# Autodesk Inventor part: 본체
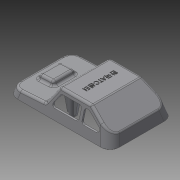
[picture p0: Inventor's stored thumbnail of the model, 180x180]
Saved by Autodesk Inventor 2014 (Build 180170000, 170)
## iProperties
Created: 2015-05
Part Number: 본체
Material: Generic
Document SubType Name: Modeling
Designer: Administrator
Density: 1 g/cm^3
Appearance: Default
Mass: 30.9016 g
Surface Area: 310.511 cm^2
Volume: 30.9016 cm^3
Author: Administrator
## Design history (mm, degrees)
sketch "스케치1"
  geometry: L1 (-61, -38)-(61, -38); L2 (61, -38)-(61, 38); L3 (61, 38)-(-61, 38); L4 (-61, 38)-(-61, -38); L5 (-61, -38)-(61, 38); L6 (61, -38)-(-61, 38); 1 further point
  constraints: 12 end point, 2 midpoint, 2 parallel, 1 horizontal, 1 perpendicular
  dimensions: "d0" = 122 distance of L3.end L2.end; "d1" = 76 distance of L2.end L1.end
extrude "돌출1" new body sketch "스케치1" distance "d2" = 30; taper "d3" = -15 deg
sketch "스케치3"
  geometry: L1 (-31, 30)-(-61, 30); L2 (-61, 30)-(-61, 10); L3 (-61, 10)-(-31, 30); L4 (52.962, 30)-(-52.962, 30) reference; L5 (-61, 0)-(61, 0) reference; 1 further point
  constraints: 6 end point, 1 collinear, 1 horizontal, 1 perpendicular, 1 point on line
  dimensions: "d4" = 30 distance from line of L2 L1.start; "d5" = 20 distance from line of L2.end L1
extrude "돌출2" cut sketch "스케치3" stored distance "d6" = 30; taper "d7" = 0 deg
sketch "스케치4"
  geometry: L1 (61, 8)-(19, 10.201); L2 (19, 10.201)-(6.628, 30); L3 (52.962, 30)-(-31, 30) reference; L4 (61, 8)-(61, 0); L5 (61, 0)-(52.962, 30) reference; L6 (-61, 0)-(61, 0) reference; L7 (6.628, 30)-(61, 30); L8 (61, 30)-(61, 8); 1 further point
  constraints: 10 end point, 2 perpendicular, 1 parallel, 1 point on line
  dimensions: "d8" = 8 distance of L4.end L1.start; "d9" = 3 deg angle of L6 L1; "d10" = 42 horizontal distance of L1.end L1.start; "d11" = 125 deg angle of L1 L2
extrude "돌출3" cut sketch "스케치4" stored distance "d12" = 30; taper "d13" = 0 deg
fillet "모깎기1" dims "d14" = 12
fillet "모깎기2" dims "d15" = 3
sketch "스케치5"
  geometry: L1 (-29.915, 45.985)-(-9.915, 45.985); L2 (-9.915, 45.985)-(-9.915, 19.985); L3 (-9.915, 19.985)-(-29.915, 19.985); L4 (-29.915, 19.985)-(-29.915, 45.985); L5 (-40.915, 59.394)-(-40.915, 6.577) reference; 2 further points
  constraints: 8 end point, 2 parallel, 1 horizontal, 1 horizontal alignment, 1 midpoint, 1 perpendicular
  dimensions: "d16" = 11 distance between parallel lines of L4 L5; "d17" = 20 distance between parallel lines of L2 L4; "d18" = 26 distance between parallel lines of L3 L1
extrude "돌출4" join sketch "스케치5" distance "d19" = 5; taper "d20" = 0 deg
node "작업 평면1"
sketch "스케치6"
  geometry: L1 (-26.409, 0)-(-38, 0) reference; L2 (38, 0)-(26.409, 0) reference; L3 (-25, 0)-(-17, 0); L4 (-14, 0)-(-6, 0); L5 (6, 0)-(14, 0); L6 (17, 0)-(25, 0); A1 r 4 centre (-10, 0) between (-6, 0) and (-14, 0); A2 r 4 centre (-21, 0) between (-17, 0) and (-25, 0); A3 r 4 centre (10, 0) between (14, 0) and (6, 0); A4 r 4 centre (21, 0) between (25, 0) and (17, 0); 1 further point
  constraints: 8 end point, 8 point on circle, 4 centre point, 4 horizontal alignment, 9 other
  dimensions: "d24" = 8 diameter of A1; "d25" = 8 diameter of A2; "d26" = 8 diameter of A3; "d27" = 8 diameter of A4; "d28" = 10 distance of point (0, 0) A1.centre; "d29" = 20 distance of A3.centre A1.centre; "d30" = 11 distance of A1.centre A2.centre; "d31" = 11 distance of A3.centre A4.centre
feature "쉘1" dims "d32" = 2
extrude "돌출5" join sketch "스케치6" stored distance "d33" = 5; taper "d34" = 0 deg
sketch "스케치7"
  geometry: L1 (-58.929, -26.27)-(-58.929, 26.27) reference; L2 (-49.27, 35.929)-(49.27, 35.929) reference; L3 (58.929, 26.27)-(58.929, -26.27) reference; L4 (49.27, -35.929)-(-49.27, -35.929) reference; L5 (49.27, 36.929)-(-49.27, 36.929); L6 (-59.929, 26.27)-(-59.929, -26.27); L7 (-49.27, -36.929)-(49.27, -36.929); L8 (59.929, -26.27)-(59.929, 26.27); 5 further points; 4 other entities
  constraints: 8 end point, 7 parallel, 16 other
  dimensions: "d35" = 1 distance between parallel lines of L2 L5
extrude "돌출6" join sketch "스케치7" distance "d36" = 1; taper "d37" = 0 deg
sketch "스케치8"
  geometry: L1 (4.965, 30)-(-30.092, 30) reference; L2 (18.172, 11.526)-(7.51, 28.59) reference; L3 (-31.756, 29.496)-(-46.213, 19.858) reference; L4 (13.23, 10)-(3.857, 25); L5 (3.857, 25)-(-20.77, 25); L6 (-20.77, 25)-(-20.77, 10); L7 (13.23, 10)-(-20.77, 10); L8 (-23.986, 25)-(-29.486, 25); L9 (-29.486, 25)-(-51.986, 10); L10 (-51.986, 10)-(-23.986, 10); L11 (-23.986, 10)-(-23.986, 25); 1 further point
  constraints: 16 end point, 5 parallel, 3 perpendicular
  dimensions: "d38" = 5 distance between parallel lines of L4 L2; "d39" = 5 distance between parallel lines of L5 L1; "d40" = 34 distance from line of L6 L4.start; "d41" = 15 distance between parallel lines of L7 L5; "d42" = 5 distance between parallel lines of L8 L1; "d43" = 5 distance between parallel lines of L3 L9; "d44" = 15 distance between parallel lines of L10 L8; "d45" = 28 distance from line of L11 L9.end
extrude "돌출7" cut sketch "스케치8" stored distance "d46" = 1; taper "d47" = 0 deg
fillet "모깎기5" dims "d48" = 3
fillet "모깎기6" dims "d49" = 3
sketch "스케치9"
  geometry: C1 r 3 at (0, -22); C2 r 3 at (0, 22); C3 r 3 at (40, 0); C4 r 3 at (-40, 0); 1 further point
  constraints: 4 centre point, 2 horizontal alignment, 2 vertical alignment
  dimensions: "d50" = 6 diameter of C1; "d51" = 6 diameter of C2; "d52" = 6 diameter of C3; "d53" = 6 diameter of C4; "d54" = 40 distance of point (0, 0) C4.centre; "d55" = 40 distance of point (0, 0) C3.centre; "d56" = 44 distance of C2.centre C1.centre; "d57" = 22 distance of C2.centre point (0, 0)
extrude "돌출8" join sketch "스케치9" stored distance "d58" = 2; taper "d59" = 2 deg
node "작업 평면2"
sketch "스케치10"
  geometry: L1 (5, -21)-(-5, -21); L2 (-5, -21)-(-5, -23); L3 (-5, -23)-(5, -23); L4 (5, -23)-(5, -21); L5 (5, -21)-(-5, -23); L6 (-5, -21)-(5, -23); L7 (-35, 1)-(-45, 1); L8 (-45, 1)-(-45, -1); L9 (-45, -1)-(-35, -1); L10 (-35, -1)-(-35, 1); L11 (-35, 1)-(-45, -1); L12 (-45, 1)-(-35, -1); L13 (5, 23)-(-5, 23); L14 (-5, 23)-(-5, 21); L15 (-5, 21)-(5, 21); L16 (5, 21)-(5, 23); L17 (5, 23)-(-5, 21); L18 (-5, 23)-(5, 21); L19 (45, 1)-(35, 1); L20 (35, 1)-(35, -1); L21 (35, -1)-(45, -1); L22 (45, -1)-(45, 1); L23 (45, 1)-(35, -1); L24 (35, 1)-(45, -1); C1 r 3 at (0, -22) reference; C2 r 3 at (-40, 0) reference; C3 r 3 at (0, 22) reference; C4 r 3 at (40, 0) reference; 1 further point
  constraints: 48 end point, 8 midpoint, 8 parallel, 4 horizontal, 4 perpendicular
  dimensions: "d61" = 10 distance of L3.end L2.end; "d62" = 2 distance of L2.end L1.end; "d63" = 10 distance of L9.end L8.end; "d64" = 2 distance of L8.end L7.end; "d65" = 10 distance of L15.end L14.end; "d66" = 2 distance of L14.end L13.end; "d67" = 10 distance of L21.end L20.end; "d68" = 2 distance of L20.end L19.end
extrude "돌출9" join sketch "스케치10" stored distance "d69" = 2; taper "d70" = 2.5 deg
sketch "스케치11"
  geometry: L1 (-35, 2)-(-33.969, 25.617) reference; L2 (-45, 2)-(-45.69, 17.803) reference; L3 (-45.103, 18.194)-(-30.646, 27.832) reference; L4 (-30.092, 28)-(4.965, 28) reference; L5 (-55.687, 11.138)-(-45.103, 18.194) reference; L6 (-37.098, 2)-(-35, 2) reference; L7 (-45, 2)-(-42.902, 2) reference; L8 (-35, 2)-(-30.426, 27.943); L9 (-40, 32.999)-(-40, -19.284); L10 (-43, 0)-(-37, 0) reference; L11 (-45, 2)-(-47.566, 16.552); L12 (33.718, 14.437)-(47.699, 13.704) reference; L13 (47.832, 8.69)-(56.649, 8.228) reference; L14 (35, 2)-(34.546, 12.39) reference; L15 (45, 2)-(45.429, 11.82) reference; L16 (35, 2)-(37.098, 2) reference; L17 (42.902, 2)-(45, 2) reference; L18 (-44.549, 17.621)-(-49.27, 0) reference; L19 (49.27, 0)-(-49.27, 0) reference; L20 (49.27, 0)-(47.675, 5.953) reference; L21 (47.675, 5.953)-(20.403, 7.382) reference; L22 (15.628, 10.195)-(4.965, 27.259) reference; L23 (4.965, 27.259)-(-30.092, 27.259) reference; L24 (-30.092, 27.259)-(-44.549, 17.621) reference; L25 (-43.742, 15.496)-(-30.242, 24.496) reference; L26 (-28.578, 25)-(-26.986, 25) reference; L27 (-23.986, 22)-(-23.986, 13) reference; L28 (-26.986, 10)-(-42.078, 10) reference; L29 (7.818, 10)-(-17.77, 10) reference; L30 (-20.77, 13)-(-20.77, 22) reference; L31 (-17.77, 25)-(2.194, 25) reference; L32 (4.738, 23.59)-(10.362, 14.59) reference; L33 (37, 0)-(36.93, 2) reference; L34 (43, 0)-(43.07, 2) reference; L35 (40, 14.107)-(40, -7.314); L36 (35, 2)-(32.823, 14.348); L37 (45, 2)-(47.07, 13.737); L38 (33.613, 12.439)-(47.594, 11.707) reference; A1 r 1 centre (-30.092, 27) between (-30.092, 28) and (-30.646, 27.832) reference; A2 r 3 centre (33.561, 11.441) between (33.718, 14.437) and (30.633, 12.095) reference; A3 r 3 centre (27.706, 12.749) between (27.549, 9.753) and (30.633, 12.095) reference; A4 r 3 centre (47.542, 10.708) between (50.522, 11.053) and (47.699, 13.704) reference; A5 r 3 centre (53.502, 11.397) between (50.522, 11.053) and (53.345, 8.401) reference; A6 r 6 centre (20.717, 13.374) between (15.628, 10.195) and (20.403, 7.382) reference; A7 r 3 centre (-42.078, 13) between (-43.742, 15.496) and (-42.078, 10) reference; A8 r 3 centre (-28.578, 22) between (-28.578, 25) and (-30.242, 24.496) reference; A9 r 3 centre (-26.986, 22) between (-23.986, 22) and (-26.986, 25) reference; A10 r 3 centre (-26.986, 13) between (-26.986, 10) and (-23.986, 13) reference; A11 r 3 centre (-17.77, 13) between (-20.77, 13) and (-17.77, 10) reference; A12 r 3 centre (-17.77, 22) between (-17.77, 25) and (-20.77, 22) reference; A13 r 3 centre (2.194, 22) between (4.738, 23.59) and (2.194, 25) reference; A14 r 3 centre (7.818, 13) between (7.818, 10) and (10.362, 14.59) reference; A15 r 1 centre (33.561, 11.441) between (33.613, 12.439) and (32.585, 11.659) reference; 2 further points
  constraints: 12 end point, 4 point on line, 2 perpendicular, 2 point on circle, 1 midpoint
  dimensions: "d71" = 10 deg angle of L8 L9; "d72" = 10 deg angle of L9 L11; "d73" = 40 distance from line of L35 point (0, 0); "d74" = 10 deg angle of L35 L36; "d75" = 10 deg angle of L35 L37
  node "투영된 루프3"
extrude "돌출10" join sketch "스케치11" stored distance "d76" = 2; taper "d77" = 0 deg
extrude "돌출11" join sketch "스케치11" stored distance "d78" = 2; taper "d79" = 0 deg
node "작업 평면3"
sketch "스케치12"
  geometry: L1 (-30.092, 28)-(4.965, 28) reference; L2 (-5, 2)-(-6.135, 28) reference; L3 (5, 2)-(6.095, 27.079) reference; L4 (5.813, 27.53)-(16.476, 10.466) reference; L5 (2.902, 2)-(5, 2) reference; L6 (-5, 2)-(-2.902, 2) reference; L7 (5, 2)-(8.69, 22.927); L8 (-5, 2)-(-9.585, 28); L9 (0, 0)-(0, 28)
  constraints: 6 end point, 3 point on line, 1 perpendicular
  dimensions: "d81" = 10 deg angle of L9 L8; "d82" = 10 deg angle of L9 L7
extrude "돌출12" join sketch "스케치12" stored distance "d83" = 2; taper "d84" = 0 deg
extrude "돌출13" join sketch "스케치12" stored distance "d85" = 2; taper "d86" = 0 deg
sketch "스케치13"
  geometry: C1 r 3 at (0, 0) reference; C2 r 3 at (40, -22) reference; C3 r 3 at (0, -44) reference; C4 r 3 at (-40, -22) reference; 5 further points
  constraints: 4 coincident
hole "구멍1" sketch "스케치13" at (0, 0), (40, -22), (0, -44), (-40, -22) diameter "d87" = 3.242; stored, may be unused: countersink angle "d91" = 90 deg, drill point angle "d93" = 118 deg; dims "d88" = 9, "d89" = 4, "d90" = 2, "d92" = 11
chamfer "모따기1" distance "d94" = 1; stored, may be unused: second distance "d95" = 2, angle "d96" = 45 deg
sketch "스케치14"
  geometry: L1 (61, -26.409)-(61, 26.409) reference; 2 further points
  constraints: 1 horizontal alignment, 1 other
  dimensions: "d97" = 50 distance from line of point (11, 0) L1
feature "엠보싱1" sketch "스케치14" dims "d98" = 0.5, "d99" = 0
sketch "스케치15"
  geometry: L1 (30.722, 14.594)-(50.695, 13.547) reference; L2 (50.433, 8.554)-(50.695, 13.547) reference; L3 (30.461, 9.601)-(30.722, 14.594) reference; L4 (47.832, 8.69)-(20.56, 10.119) reference; L5 (47.832, 8.69)-(56.649, 8.228) reference; L6 (50.433, 8.554)-(48.878, 13.642); L7 (30.461, 9.601)-(32.54, 14.498); L8 (48.878, 13.642)-(50.695, 13.547); L9 (50.433, 8.554)-(50.695, 13.547); L10 (32.595, 14.496)-(30.722, 14.594); L11 (30.722, 14.594)-(30.461, 9.601); 1 further point
  constraints: 12 end point, 3 collinear, 3 point on line, 1 perpendicular
  dimensions: "d100" = 110 deg angle of L5 L6; "d101" = 110 deg angle of L7 L4
extrude "돌출14" cut sketch "스케치15" stored distance "d102" = 10; taper "d103" = 0 deg
fillet "모깎기7" dims "d104" = 3
fillet "모깎기8" dims "d105" = 3
fillet "모깎기9" dims "d106" = 3
fillet "모깎기10" dims "d107" = 3
fillet "모깎기11" dims "d108" = 3
node "솔리드1"
mirror "대칭2"
node "투영된 루프1"
node "투영된 루프2"
node "투영된 루프4"
node "투영된 루프5"
node "투영된 루프6"
other parameters: "d23" = -63, "d60" = 2, "d80" = 22
